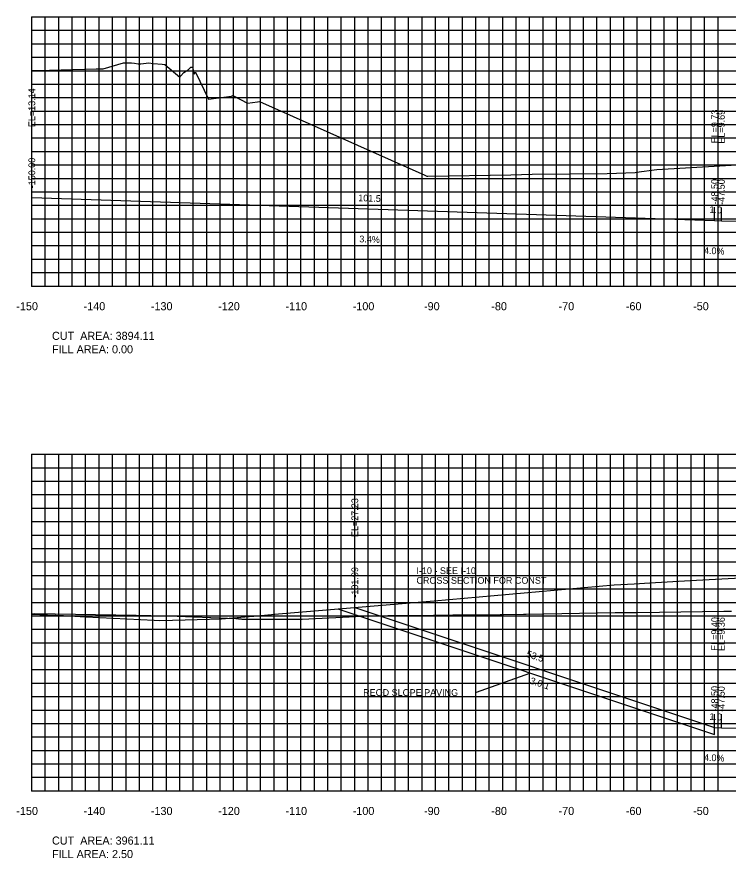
# Model space of a CAD drawing. Extents: x 1797789 to 1803805, y 249066 to 250293.
# Drawn here: x 1802478.8 to 1802584.5, y 250089.4 to 250214.4 of the extents above; entities that cross this region are included whole.
import ezdxf

# ---------------------------------------------------------------- set-up
doc = ezdxf.new("R2010")
doc.units = 0
for name, color, linetype in [('10', 7, 'Continuous'), ('3', 7, 'Continuous'), ('4', 7, 'Continuous'), ('60', 7, 'Continuous'), ('ANNO-TXT', 7, 'Continuous'), ('CL-CNST', 7, 'Continuous'), ('Level 62', 7, 'Continuous'), ('M-ROADS', 7, 'Continuous')]:
    doc.layers.add(name, color=color, linetype=linetype)

msp = doc.modelspace()

# ---------------------------------------------------------------- linework, layer by layer
for p, q in [((1802481, 250187.57), (1802481, 250189.57)), ((1802582.5, 250184.16), (1802582.5, 250186.16)), ((1802583.5, 250184.12), (1802583.5, 250186.12)), ((1802529.01, 250126.66), (1802529.01, 250128.66)), ((1802582.5, 250108.83), (1802582.5, 250110.83)), ((1802583.5, 250108.79), (1802583.5, 250110.79))]:
    msp.add_line(p, q)
at = {"layer": '3'}
msp.add_line((1802547.1, 250114.08), (1802555.04, 250116.93), dxfattribs=at)
at = {"layer": '60'}
for p, q in [((1802480.94, 250214.43), (1802481, 250214.43)), ((1802481, 250174.43), (1802481, 250214.43)), ((1802480.94, 250204.43), (1802481, 250204.43)), ((1802480.94, 250194.43), (1802481, 250194.43)), ((1802480.94, 250184.43), (1802481, 250184.43)), ((1802480.94, 250174.43), (1802481, 250174.43)), ((1802481, 250174.43), (1802781, 250174.43)), ((1802481, 250174.37), (1802481, 250174.43)), ((1802491, 250174.37), (1802491, 250174.43)), ((1802501, 250174.37), (1802501, 250174.43)), ((1802511, 250174.37), (1802511, 250174.43)), ((1802521, 250174.37), (1802521, 250174.43)), ((1802531, 250174.37), (1802531, 250174.43)), ((1802541, 250174.37), (1802541, 250174.43)), ((1802551, 250174.37), (1802551, 250174.43)), ((1802561, 250174.37), (1802561, 250174.43)), ((1802571, 250174.37), (1802571, 250174.43)), ((1802581, 250174.37), (1802581, 250174.43)), ((1802480.94, 250149.43), (1802481, 250149.43)), ((1802481, 250099.43), (1802481, 250149.43)), ((1802480.94, 250139.43), (1802481, 250139.43)), ((1802480.94, 250129.43), (1802481, 250129.43)), ((1802480.94, 250119.43), (1802481, 250119.43)), ((1802480.94, 250109.43), (1802481, 250109.43)), ((1802480.94, 250099.43), (1802481, 250099.43)), ((1802481, 250099.43), (1802781, 250099.43)), ((1802481, 250099.37), (1802481, 250099.43)), ((1802491, 250099.37), (1802491, 250099.43)), ((1802501, 250099.37), (1802501, 250099.43)), ((1802511, 250099.37), (1802511, 250099.43)), ((1802521, 250099.37), (1802521, 250099.43)), ((1802531, 250099.37), (1802531, 250099.43)), ((1802541, 250099.37), (1802541, 250099.43)), ((1802551, 250099.37), (1802551, 250099.43)), ((1802561, 250099.37), (1802561, 250099.43)), ((1802571, 250099.37), (1802571, 250099.43)), ((1802581, 250099.37), (1802581, 250099.43))]:
    msp.add_line(p, q, dxfattribs=at)
at = {"layer": 'CL-CNST'}
for p, q in [((1802526.49, 250126.45), (1802582.5, 250107.78)), ((1802582.5, 250107.78), (1802582.5, 250108.83))]:
    msp.add_line(p, q, dxfattribs=at)
for points in [[(1802481, 250187.57), (1802582.5, 250184.16), (1802583.5, 250184.12), (1802590.5, 250184.02), (1802590.5, 250184.02), (1802590.83, 250184.02), (1802591, 250183.52), (1802593, 250183.68), (1802597, 250183.77), (1802631, 250184.51), (1802665, 250183.77), (1802669, 250183.68), (1802671, 250183.52), (1802671.17, 250184.02), (1802671.5, 250184.02), (1802671.5, 250184.02), (1802678.5, 250184.12), (1802679.5, 250184.16), (1802781, 250184.59)], [(1802481, 250125.67), (1802485.7, 250125.45), (1802489.05, 250125.3), (1802499.2, 250124.76), (1802500.03, 250124.72), (1802503.77, 250124.83), (1802509.21, 250124.99), (1802512.64, 250125.27), (1802514, 250125.39), (1802517.65, 250125.7), (1802540.82, 250127.67), (1802567.56, 250130.03), (1802570.52, 250130.2), (1802572.85, 250130.32), (1802578.86, 250130.66), (1802593.99, 250131.49), (1802594.15, 250131.5), (1802594.36, 250131.51), (1802632.25, 250133.61), (1802645.42, 250134.34), (1802646.58, 250134.41)], [(1802529.01, 250126.66), (1802582.5, 250108.83), (1802583.5, 250108.79), (1802590.5, 250108.69), (1802590.5, 250108.69), (1802590.83, 250108.69), (1802591, 250108.19), (1802593, 250108.35), (1802597, 250108.44), (1802631, 250109.18), (1802665, 250108.44), (1802669, 250108.35), (1802671, 250108.19), (1802671.17, 250108.69), (1802671.5, 250108.69), (1802671.5, 250108.69), (1802678.5, 250108.79), (1802679.5, 250108.83), (1802781, 250109.41)]]:
    msp.add_lwpolyline(points, dxfattribs=at)
at = {"layer": 'Level 62'}
for p, q in [((1802481, 250214.43), (1802781, 250214.43)), ((1802481, 250174.43), (1802481, 250214.43)), ((1802483, 250174.43), (1802483, 250214.43)), ((1802485, 250174.43), (1802485, 250214.43)), ((1802487, 250174.43), (1802487, 250214.43)), ((1802489, 250174.43), (1802489, 250214.43)), ((1802491, 250174.43), (1802491, 250214.43)), ((1802493, 250174.43), (1802493, 250214.43)), ((1802495, 250174.43), (1802495, 250214.43)), ((1802497, 250174.43), (1802497, 250214.43)), ((1802499, 250174.43), (1802499, 250214.43)), ((1802501, 250174.43), (1802501, 250214.43)), ((1802503, 250174.43), (1802503, 250214.43)), ((1802505, 250174.43), (1802505, 250214.43)), ((1802507, 250174.43), (1802507, 250214.43)), ((1802509, 250174.43), (1802509, 250214.43)), ((1802511, 250174.43), (1802511, 250214.43)), ((1802513, 250174.43), (1802513, 250214.43)), ((1802515, 250174.43), (1802515, 250214.43)), ((1802517, 250174.43), (1802517, 250214.43)), ((1802519, 250174.43), (1802519, 250214.43)), ((1802521, 250174.43), (1802521, 250214.43)), ((1802523, 250174.43), (1802523, 250214.43)), ((1802525, 250174.43), (1802525, 250214.43)), ((1802527, 250174.43), (1802527, 250214.43)), ((1802529, 250174.43), (1802529, 250214.43)), ((1802531, 250174.43), (1802531, 250214.43)), ((1802533, 250174.43), (1802533, 250214.43)), ((1802535, 250174.43), (1802535, 250214.43)), ((1802537, 250174.43), (1802537, 250214.43)), ((1802539, 250174.43), (1802539, 250214.43)), ((1802541, 250174.43), (1802541, 250214.43)), ((1802543, 250174.43), (1802543, 250214.43)), ((1802545, 250174.43), (1802545, 250214.43)), ((1802547, 250174.43), (1802547, 250214.43)), ((1802549, 250174.43), (1802549, 250214.43)), ((1802551, 250174.43), (1802551, 250214.43)), ((1802553, 250174.43), (1802553, 250214.43)), ((1802555, 250174.43), (1802555, 250214.43)), ((1802557, 250174.43), (1802557, 250214.43)), ((1802559, 250174.43), (1802559, 250214.43)), ((1802561, 250174.43), (1802561, 250214.43)), ((1802563, 250174.43), (1802563, 250214.43)), ((1802565, 250174.43), (1802565, 250214.43)), ((1802567, 250174.43), (1802567, 250214.43)), ((1802569, 250174.43), (1802569, 250214.43)), ((1802571, 250174.43), (1802571, 250214.43)), ((1802573, 250174.43), (1802573, 250214.43)), ((1802575, 250174.43), (1802575, 250214.43)), ((1802577, 250174.43), (1802577, 250214.43)), ((1802579, 250174.43), (1802579, 250214.43)), ((1802581, 250174.43), (1802581, 250214.43)), ((1802583, 250174.43), (1802583, 250214.43)), ((1802481, 250212.43), (1802781, 250212.43)), ((1802481, 250210.43), (1802781, 250210.43)), ((1802481, 250208.43), (1802781, 250208.43)), ((1802481, 250206.43), (1802781, 250206.43)), ((1802481, 250204.43), (1802781, 250204.43)), ((1802481, 250202.43), (1802781, 250202.43)), ((1802481, 250200.43), (1802781, 250200.43)), ((1802481, 250198.43), (1802781, 250198.43)), ((1802481, 250196.43), (1802781, 250196.43)), ((1802481, 250194.43), (1802781, 250194.43)), ((1802481, 250192.43), (1802781, 250192.43)), ((1802481, 250190.43), (1802781, 250190.43)), ((1802481, 250188.43), (1802781, 250188.43)), ((1802481, 250186.43), (1802781, 250186.43)), ((1802481, 250184.43), (1802781, 250184.43)), ((1802481, 250182.43), (1802781, 250182.43)), ((1802481, 250180.43), (1802781, 250180.43)), ((1802481, 250178.43), (1802781, 250178.43)), ((1802481, 250176.43), (1802781, 250176.43)), ((1802481, 250174.43), (1802781, 250174.43)), ((1802481, 250149.43), (1802781, 250149.43)), ((1802481, 250099.43), (1802481, 250149.43)), ((1802483, 250099.43), (1802483, 250149.43)), ((1802485, 250099.43), (1802485, 250149.43)), ((1802487, 250099.43), (1802487, 250149.43)), ((1802489, 250099.43), (1802489, 250149.43)), ((1802491, 250099.43), (1802491, 250149.43)), ((1802493, 250099.43), (1802493, 250149.43)), ((1802495, 250099.43), (1802495, 250149.43)), ((1802497, 250099.43), (1802497, 250149.43)), ((1802499, 250099.43), (1802499, 250149.43)), ((1802501, 250099.43), (1802501, 250149.43)), ((1802503, 250099.43), (1802503, 250149.43)), ((1802505, 250099.43), (1802505, 250149.43)), ((1802507, 250099.43), (1802507, 250149.43)), ((1802509, 250099.43), (1802509, 250149.43)), ((1802511, 250099.43), (1802511, 250149.43)), ((1802513, 250099.43), (1802513, 250149.43)), ((1802515, 250099.43), (1802515, 250149.43)), ((1802517, 250099.43), (1802517, 250149.43)), ((1802519, 250099.43), (1802519, 250149.43)), ((1802521, 250099.43), (1802521, 250149.43)), ((1802523, 250099.43), (1802523, 250149.43)), ((1802525, 250099.43), (1802525, 250149.43)), ((1802527, 250099.43), (1802527, 250149.43)), ((1802529, 250099.43), (1802529, 250149.43)), ((1802531, 250099.43), (1802531, 250149.43)), ((1802533, 250099.43), (1802533, 250149.43)), ((1802535, 250099.43), (1802535, 250149.43)), ((1802537, 250099.43), (1802537, 250149.43)), ((1802539, 250099.43), (1802539, 250149.43)), ((1802541, 250099.43), (1802541, 250149.43)), ((1802543, 250099.43), (1802543, 250149.43)), ((1802545, 250099.43), (1802545, 250149.43)), ((1802547, 250099.43), (1802547, 250149.43)), ((1802549, 250099.43), (1802549, 250149.43)), ((1802551, 250099.43), (1802551, 250149.43)), ((1802553, 250099.43), (1802553, 250149.43)), ((1802555, 250099.43), (1802555, 250149.43)), ((1802557, 250099.43), (1802557, 250149.43)), ((1802559, 250099.43), (1802559, 250149.43)), ((1802561, 250099.43), (1802561, 250149.43)), ((1802563, 250099.43), (1802563, 250149.43)), ((1802565, 250099.43), (1802565, 250149.43)), ((1802567, 250099.43), (1802567, 250149.43)), ((1802569, 250099.43), (1802569, 250149.43)), ((1802571, 250099.43), (1802571, 250149.43)), ((1802573, 250099.43), (1802573, 250149.43)), ((1802575, 250099.43), (1802575, 250149.43)), ((1802577, 250099.43), (1802577, 250149.43)), ((1802579, 250099.43), (1802579, 250149.43)), ((1802581, 250099.43), (1802581, 250149.43)), ((1802583, 250099.43), (1802583, 250149.43)), ((1802481, 250147.43), (1802781, 250147.43)), ((1802481, 250145.43), (1802781, 250145.43)), ((1802481, 250143.43), (1802781, 250143.43)), ((1802481, 250141.43), (1802781, 250141.43)), ((1802481, 250139.43), (1802781, 250139.43)), ((1802481, 250137.43), (1802781, 250137.43)), ((1802481, 250135.43), (1802781, 250135.43)), ((1802481, 250133.43), (1802781, 250133.43)), ((1802481, 250131.43), (1802781, 250131.43)), ((1802481, 250129.43), (1802781, 250129.43)), ((1802481, 250127.43), (1802781, 250127.43)), ((1802481, 250125.43), (1802781, 250125.43)), ((1802481, 250123.43), (1802781, 250123.43)), ((1802481, 250121.43), (1802781, 250121.43)), ((1802481, 250119.43), (1802781, 250119.43)), ((1802481, 250117.43), (1802781, 250117.43)), ((1802481, 250115.43), (1802781, 250115.43)), ((1802481, 250113.43), (1802781, 250113.43)), ((1802481, 250111.43), (1802781, 250111.43)), ((1802481, 250109.43), (1802781, 250109.43)), ((1802481, 250107.43), (1802781, 250107.43)), ((1802481, 250105.43), (1802781, 250105.43)), ((1802481, 250103.43), (1802781, 250103.43)), ((1802481, 250101.43), (1802781, 250101.43)), ((1802481, 250099.43), (1802781, 250099.43))]:
    msp.add_line(p, q, dxfattribs=at)
at = {"layer": 'M-ROADS'}
for points in [[(1802481, 250206.47), (1802481.32, 250206.46), (1802481.93, 250206.47), (1802482.68, 250206.48), (1802483.61, 250206.5), (1802490.56, 250206.68), (1802491.62, 250206.7), (1802494.64, 250207.58), (1802495.19, 250207.6), (1802495.23, 250207.6), (1802495.82, 250207.6), (1802496.28, 250207.53), (1802496.82, 250207.47), (1802497.19, 250207.43), (1802498.41, 250207.6), (1802499.03, 250207.5), (1802500.37, 250207.42), (1802500.77, 250207.34), (1802502.98, 250205.48), (1802503.16, 250205.67), (1802503.61, 250206.16), (1802504.22, 250206.54), (1802504.62, 250206.95), (1802504.78, 250206.95), (1802504.89, 250206.95), (1802505.14, 250205.91), (1802505.2, 250206.06), (1802505.32, 250206.1), (1802505.35, 250206.2), (1802507.25, 250202.19), (1802510.69, 250202.65), (1802510.88, 250202.75), (1802513.07, 250201.62), (1802514.55, 250201.8), (1802514.84, 250201.87), (1802539.44, 250190.9), (1802539.71, 250190.78), (1802539.71, 250190.78), (1802539.74, 250190.77), (1802539.75, 250190.77), (1802539.86, 250190.76), (1802552.2, 250190.94), (1802555.37, 250191.04), (1802566.51, 250191.17), (1802570.67, 250191.32), (1802570.88, 250191.34), (1802573.92, 250191.76), (1802588.37, 250192.57)], [(1802481, 250125.75), (1802481.26, 250125.74), (1802481.43, 250125.75), (1802496.52, 250125.51), (1802500.88, 250125.43), (1802501.03, 250125.45), (1802501.36, 250125.44), (1802511.34, 250125.05), (1802511.36, 250125.04), (1802511.37, 250125.04), (1802511.39, 250125.04), (1802511.41, 250125.04), (1802511.44, 250125.04), (1802511.46, 250125.03), (1802511.49, 250125.03), (1802511.53, 250125.03), (1802511.57, 250125.02), (1802511.61, 250125.02), (1802511.67, 250125.01), (1802511.74, 250125), (1802511.83, 250124.99), (1802511.95, 250124.98), (1802512.1, 250124.96), (1802512.22, 250124.95), (1802513.53, 250124.95), (1802513.56, 250124.95), (1802515.59, 250124.95), (1802517.3, 250124.95), (1802518.77, 250124.95), (1802520.04, 250124.95), (1802521.16, 250124.95), (1802530.16, 250125.36), (1802530.37, 250125.36), (1802533.94, 250125.45), (1802535.35, 250125.45), (1802537.21, 250125.48), (1802537.32, 250125.48), (1802537.78, 250125.48), (1802543.58, 250125.57), (1802550.63, 250125.6), (1802551.09, 250125.61), (1802554.08, 250125.66), (1802554.18, 250125.66), (1802554.49, 250125.65), (1802567.7, 250125.9), (1802567.84, 250125.91), (1802568.4, 250125.92), (1802570.83, 250125.92), (1802574.29, 250125.98), (1802583.86, 250126.11), (1802584.98, 250126.14)]]:
    msp.add_lwpolyline(points, dxfattribs=at)

# ---------------------------------------------------------------- texts
msp.add_text('3.0:1', height=1, rotation=341.5651).set_placement((1802554.96, 250115.38))
at = {"layer": '10'}
for s, p in [('-150', (1802478.7, 250170.83)), ('-140', (1802488.7, 250170.83)), ('-130', (1802498.7, 250170.83)), ('-120', (1802508.7, 250170.83)), ('-110', (1802518.7, 250170.83)), ('-100', (1802528.7, 250170.83)), ('-90', (1802539.3, 250170.83)), ('-80', (1802549.3, 250170.83)), ('-70', (1802559.3, 250170.83)), ('-60', (1802569.3, 250170.83)), ('-50', (1802579.3, 250170.83)), ('-150', (1802478.7, 250095.83)), ('-140', (1802488.7, 250095.83)), ('-130', (1802498.7, 250095.83)), ('-120', (1802508.7, 250095.83)), ('-110', (1802518.7, 250095.83)), ('-100', (1802528.7, 250095.83)), ('-90', (1802539.3, 250095.83)), ('-80', (1802549.3, 250095.83)), ('-70', (1802559.3, 250095.83)), ('-60', (1802569.3, 250095.83)), ('-50', (1802579.3, 250095.83))]:
    msp.add_text(s, height=1.2, dxfattribs=at).set_placement(p)
at = {"layer": '3'}
for s, p in [('EL=13.14', (1802481.5, 250198.04)), ('EL=9.73', (1802583, 250195.63)), ('EL=9.69', (1802584, 250195.59)), ('-150.00', (1802481.5, 250188.96)), ('-48.50', (1802583, 250186.54)), ('-47.50', (1802584, 250186.5)), ('EL=27.23', (1802529.51, 250137.14)), ('-101.99', (1802529.51, 250128.13)), ('EL=9.40', (1802583, 250120.22)), ('EL=9.36', (1802584, 250120.21)), ('-48.50', (1802583, 250111.21)), ('-47.50', (1802584, 250111.17))]:
    msp.add_text(s, height=1, rotation=90, dxfattribs=at).set_placement(p)
for s, p in [('I-10 - SEE I-10', (1802538.17, 250131.63)), ('CROSS SECTION FOR CONST ', (1802538.17, 250130.19)), ('REQD SLOPE PAVING', (1802530.25, 250113.53))]:
    msp.add_text(s, height=1, dxfattribs=at).set_placement(p)
at = {"layer": '4'}
for s, rotation, p in [('101.5', 358.0784, (1802529.51, 250187.04)), ('1.0', 357.7094, (1802581.72, 250185.3)), ('3.4%', 358.0784, (1802529.67, 250180.93)), ('4.0%', 357.7094, (1802580.89, 250179.22)), ('53.5', 341.5651, (1802554.42, 250119.36)), ('1.0', 357.7094, (1802581.72, 250109.97)), ('4.0%', 357.7094, (1802580.89, 250103.89))]:
    msp.add_text(s, height=1, rotation=rotation, dxfattribs=at).set_placement(p)
at = {"layer": '60'}
for p in [(1802481, 250174.43), (1802481, 250099.43)]:
    msp.add_text('-', height=0.0001, dxfattribs=at).set_placement(p)
at = {"layer": 'ANNO-TXT'}
for s, p in [('CUT  AREA: 3894.11', (1802484, 250166.43)), ('FILL AREA: 0.00', (1802484, 250164.43)), ('CUT  AREA: 3961.11', (1802484, 250091.43)), ('FILL AREA: 2.50', (1802484, 250089.43))]:
    msp.add_text(s, height=1.2, dxfattribs=at).set_placement(p)

doc.saveas('drawing.dxf')
